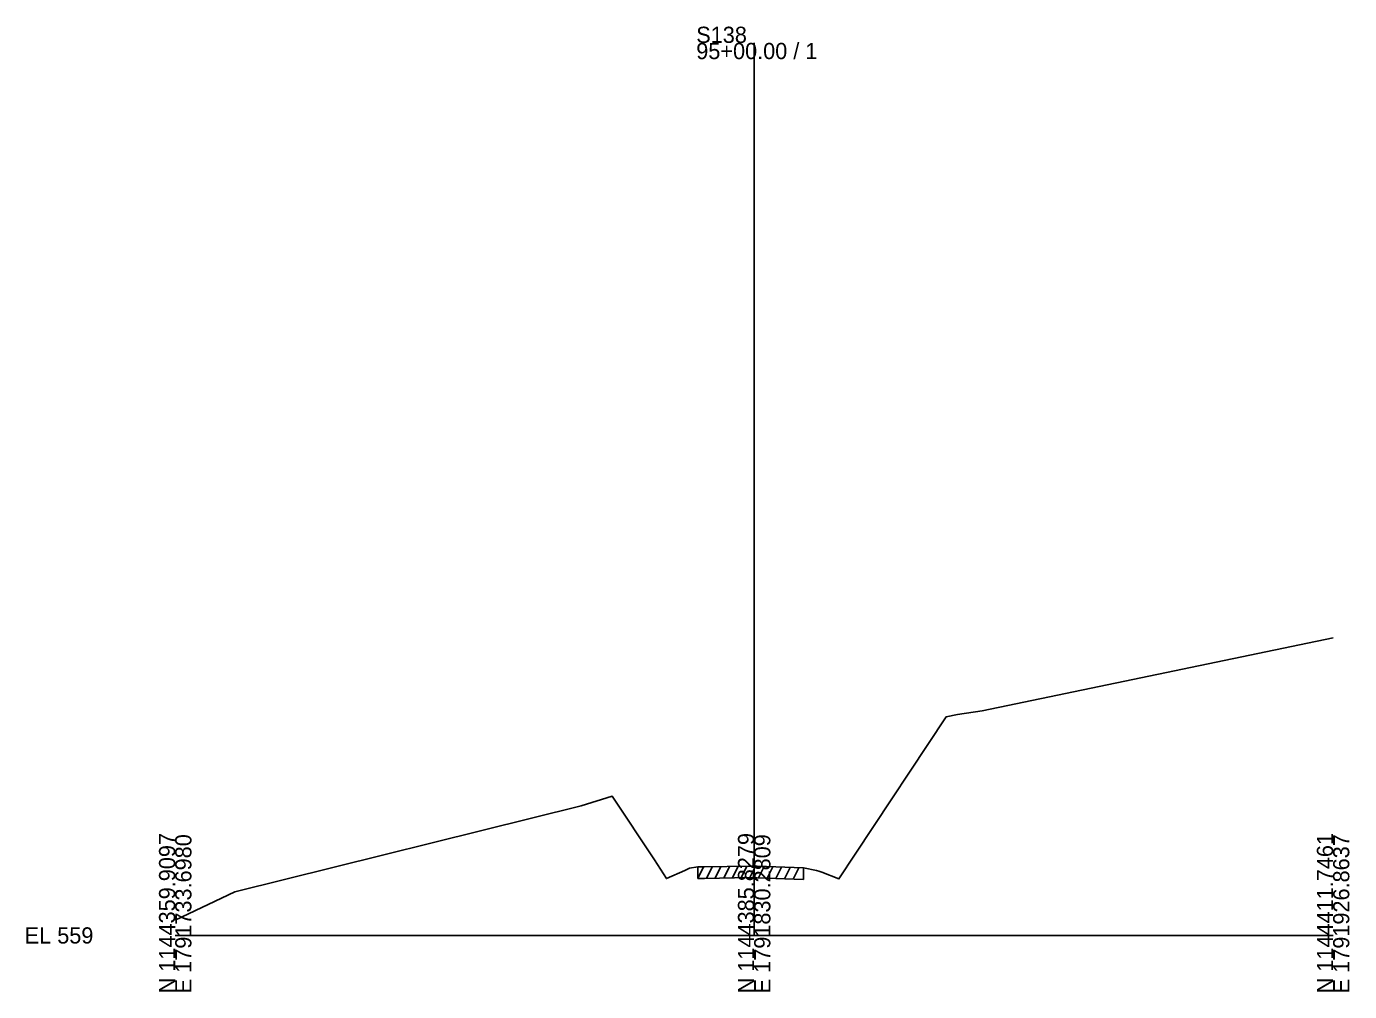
# Model space of a CAD drawing. Extents: x -26 to 1203, y -10 to 19606.
# Drawn here: x 974.3 to 1202.8, y 9990.3 to 10157 of the extents above; entities that cross this region are included whole.
import ezdxf

# ---------------------------------------------------------------- set-up
doc = ezdxf.new("R2010")
doc.units = 0
for name, color, linetype in [('RD_EX_Driveway', 7, 'Continuous'), ('RD_GPK_XS_Cell', 7, 'Continuous'), ('RD_XS_ExGround', 7, 'Continuous'), ('RD_XS_ExPaveRet', 7, 'Continuous')]:
    doc.layers.add(name, color=color, linetype=linetype)

msp = doc.modelspace()

# ---------------------------------------------------------------- linework, layer by layer
at = {"layer": 'RD_GPK_XS_Cell'}
for p, q in [((1100, 10000), (1100, 10154.18)), ((1000, 10000), (1100, 10000)), ((1100, 10000), (1200, 10000))]:
    msp.add_line(p, q, dxfattribs=at)
at = {"layer": 'RD_XS_ExGround'}
msp.add_lwpolyline([(1000, 10002.66), (1010.32, 10007.53), (1070.1, 10022.36), (1075.5, 10024.04), (1082.78, 10013.04), (1084.85, 10009.82), (1088.03, 10011.22), (1088.83, 10011.61), (1090.25, 10011.84), (1091.41, 10011.85), (1099.19, 10011.98), (1100, 10011.95), (1100.51, 10011.94), (1108.5, 10011.68), (1110.79, 10011.19), (1111.17, 10011.11), (1111.69, 10010.92), (1114.63, 10009.75), (1117.42, 10014.05), (1133.17, 10037.78), (1135.12, 10038.16), (1139.38, 10038.82), (1200, 10051.39)], dxfattribs=at)
at = {"layer": 'RD_XS_ExPaveRet'}
for p, q in [((1090.25, 10009.84), (1091.26, 10011.85)), ((1090.25, 10009.84), (1090.25, 10011.84)), ((1090.25, 10009.84), (1091.41, 10009.85)), ((1091.41, 10009.85), (1099.19, 10009.98)), ((1091.75, 10009.85), (1092.76, 10011.87)), ((1093.25, 10009.88), (1094.26, 10011.9)), ((1094.75, 10009.91), (1095.76, 10011.92)), ((1096.25, 10009.93), (1097.26, 10011.95)), ((1097.75, 10009.96), (1098.76, 10011.98)), ((1099.19, 10009.98), (1100, 10009.95)), ((1099.25, 10009.98), (1100.24, 10011.95)), ((1100, 10009.95), (1100.51, 10009.94)), ((1100.51, 10009.94), (1108.5, 10009.68)), ((1100.75, 10009.93), (1101.74, 10011.9)), ((1102.25, 10009.88), (1103.24, 10011.85)), ((1103.75, 10009.83), (1104.74, 10011.8)), ((1105.25, 10009.78), (1106.24, 10011.75)), ((1106.75, 10009.73), (1107.74, 10011.7)), ((1108.5, 10011.68), (1108.5, 10009.68))]:
    msp.add_line(p, q, dxfattribs=at)

# ---------------------------------------------------------------- texts
at = {"layer": 'RD_EX_Driveway'}
msp.add_text('564.98', height=0.0975, rotation=90, dxfattribs=at).set_placement((1100.1, 10011.95))
at = {"layer": 'RD_GPK_XS_Cell'}
for s, p in [('S138', (1090, 10154.18)), ('95+00.00 / 1', (1090, 10151.38)), ('EL 559', (974, 9998.6))]:
    msp.add_text(s, height=2.8, dxfattribs=at).set_placement(p)
for s, p in [('N 1144359.9097', (1000, 9990)), ('E 1791733.6980', (1002.8, 9990)), ('N 1144385.8279', (1100, 9990)), ('E 1791830.2809', (1102.8, 9990)), ('N 1144411.7461', (1200, 9990)), ('E 1791926.8637', (1202.8, 9990))]:
    msp.add_text(s, height=2.8, rotation=90, dxfattribs=at).set_placement(p)

doc.saveas('drawing.dxf')
